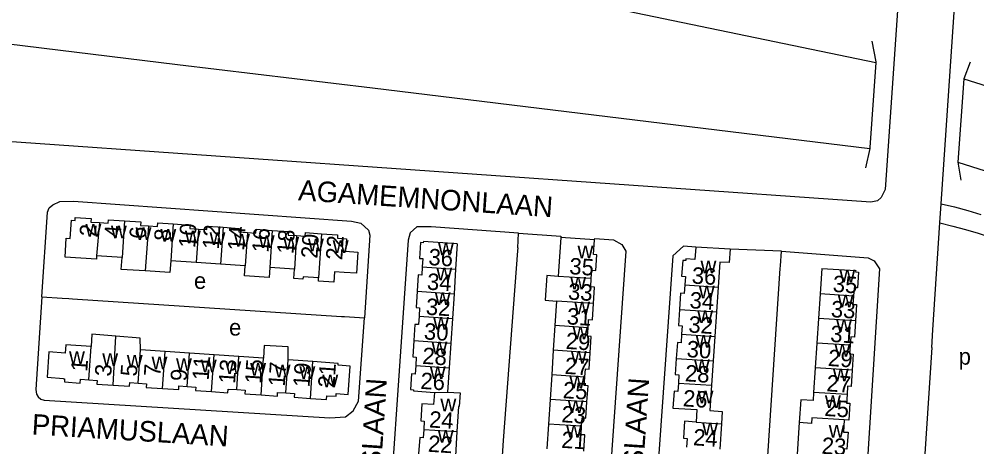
# Model space of a CAD drawing. Extents: x 161773 to 163836, y 384796 to 386521.
# Drawn here: x 162231.1 to 162464.1, y 385536.8 to 385640.8 of the extents above; entities that cross this region are included whole.
import ezdxf

# ---------------------------------------------------------------- set-up
doc = ezdxf.new("R2010")
doc.units = 0
for name, color, linetype in [('BLT_Basislijn', 7, 'Continuous'), ('BLT_Bebouwing', 7, 'Continuous'), ('BLT_Centroide', 7, 'Continuous'), ('BLT_Huisnummer', 7, 'Continuous'), ('BLT_Huisnummer_ tussenligend', 7, 'Continuous'), ('BLT_Onderverdeling_panden', 7, 'Continuous'), ('BLT_Straatnaam', 7, 'Continuous')]:
    doc.layers.add(name, color=color, linetype=linetype)

msp = doc.modelspace()

# ---------------------------------------------------------------- linework, layer by layer
at = {"layer": 'BLT_Basislijn'}
for p, q in [((162317.63, 385655.58), (162439.53, 385630.3)), ((162455.44, 385595.95), (162458.85, 385647.17)), ((162462.45, 385630.37), (162460.94, 385626.3)), ((162460.94, 385626.3), (162459.48, 385606.08)), ((162460.94, 385626.3), (162577.56, 385589.09)), ((162317.05, 385624.1), (162438.01, 385609.35)), ((162438.01, 385609.35), (162436.97, 385604.71)), ((162459.48, 385606.08), (162568.47, 385571.39)), ((162459.48, 385606.08), (162460.19, 385601.65)), ((162455.11, 385591.28), (162455.44, 385595.95)), ((162453.41, 385565.26), (162455.11, 385591.28)), ((162352.37, 385585.22), (162352.6, 385588.82)), ((162416.29, 385580.88), (162416.57, 385584.43)), ((162236.59, 385573.34), (162241.5, 385572.97)), ((162241.5, 385572.97), (162243.11, 385572.86)), ((162453.14, 385560.96), (162453.41, 385565.26)), ((162453.14, 385560.96), (162451.4, 385535.15))]:
    msp.add_line(p, q, dxfattribs=at)
for points in [[(162446.19, 385662.98), (162441.79, 385599.38), (162440.77, 385597.42), (162439.88, 385596.67), (162438.29, 385596.3), (162225.72, 385611.21)], [(162219.86, 385635.91), (162269.55, 385629.78), (162317.05, 385624.1)], [(162438.57, 385635.47), (162439.54, 385630.47), (162439.53, 385630.3)], [(162439.53, 385630.3), (162438.06, 385609.58), (162438.01, 385609.35)], [(162236.59, 385573.34), (162237.99, 385593.89), (162238.38, 385594.97), (162239.27, 385595.66), (162240.95, 385596.48)], [(162240.95, 385596.48), (162244.29, 385596.54), (162311.89, 385591.7), (162314.21, 385591.24), (162316.1, 385589.55), (162316.37, 385588.32), (162315.09, 385568.17)], [(162455.44, 385595.95), (162458.67, 385595.16), (162461.89, 385594.29), (162465.08, 385593.35)], [(162455.11, 385591.28), (162458.23, 385590.52), (162461.34, 385589.68), (162464.43, 385588.76), (162467.5, 385587.77), (162470.53, 385586.7), (162473.55, 385585.56), (162476.53, 385584.34), (162479.48, 385583.05), (162482.4, 385581.68), (162485.28, 385580.25), (162488.12, 385578.74), (162490.93, 385577.16), (162497.53, 385573.15)], [(162352.6, 385588.82), (162331.35, 385590.34), (162327.84, 385590.35), (162326.21, 385588.84), (162325.71, 385587.09), (162319.43, 385496.47), (162318.42, 385473.09), (162319.18, 385471.31), (162321.51, 385470.26), (162326.73, 385469.96)], [(162371.07, 385587.15), (162371.1, 385587.49), (162375.7, 385587.16), (162377.7, 385586.01), (162378.66, 385584.37), (162370.58, 385469.39), (162368.62, 385467.29), (162344.38, 385468.56)], [(162352.6, 385588.82), (162362.88, 385588.08), (162362.85, 385587.71)], [(162352.37, 385585.22), (162352.32, 385584.51), (162348.85, 385538.38), (162344.58, 385473.66)], [(162395.69, 385585.39), (162392.74, 385585.63), (162390.11, 385583.26), (162382.55, 385476.72), (162382.35, 385468.26), (162382.51, 385467.58), (162384.26, 385466.04), (162390.68, 385465.7)], [(162416.57, 385584.43), (162404.05, 385584.87)], [(162416.57, 385584.43), (162437.66, 385582.79), (162439.1, 385582.08), (162440.36, 385580.08), (162432.98, 385462.84)], [(162408.9, 385469.26), (162408.9, 385469.41), (162416.24, 385580.21), (162416.29, 385580.88)], [(162236.59, 385573.34), (162235.09, 385550.76), (162235.26, 385549.65), (162235.7, 385548.98), (162236.36, 385548.44), (162237.13, 385548.2)], [(162243.11, 385572.86), (162244.01, 385572.79), (162309.46, 385568.54)], [(162237.13, 385548.2), (162306.66, 385543.92), (162310.44, 385544.14), (162312.35, 385545.57), (162313.62, 385547.96), (162315.09, 385568.17)], [(162309.46, 385568.54), (162310.19, 385568.49), (162315.09, 385568.17)]]:
    msp.add_lwpolyline(points, dxfattribs=at)
at = {"layer": 'BLT_Bebouwing'}
for p, q in [((162404.05, 385584.87), (162395.69, 385585.39)), ((162256.11, 385582.84), (162249.91, 385583.25)), ((162274.12, 385581.65), (162267.93, 385582.05)), ((162280.08, 385581.25), (162274.12, 385581.65)), ((162286.05, 385580.86), (162280.08, 385581.25)), ((162298.05, 385580.06), (162292.06, 385580.46)), ((162337.26, 385580.05), (162336.87, 385574.07)), ((162401.16, 385575.65), (162400.75, 385569.64)), ((162336.87, 385574.07), (162336.47, 385568.05)), ((162425.93, 385574.03), (162425.54, 385568.05)), ((162361.83, 385572.29), (162361.43, 385566.3)), ((162336.47, 385568.05), (162336.08, 385562.06)), ((162400.75, 385569.64), (162400.35, 385563.64)), ((162425.54, 385568.05), (162425.14, 385562.06)), ((162361.43, 385566.3), (162361.03, 385560.3)), ((162400.35, 385563.64), (162399.95, 385557.71)), ((162248.56, 385561.22), (162242.43, 385561.64)), ((162336.08, 385562.06), (162335.68, 385556.03)), ((162425.14, 385562.06), (162424.75, 385556.05)), ((162266.55, 385560), (162260.56, 385560.4)), ((162272.52, 385559.59), (162266.55, 385560)), ((162278.51, 385559.18), (162272.52, 385559.59)), ((162284.53, 385558.78), (162278.51, 385559.18)), ((162290.54, 385558.37), (162284.53, 385558.78)), ((162361.03, 385560.3), (162360.64, 385554.31)), ((162302.52, 385557.55), (162296.52, 385557.96)), ((162308.71, 385557.13), (162302.52, 385557.55)), ((162399.95, 385557.71), (162399.55, 385551.79)), ((162335.68, 385556.03), (162335.3, 385550.13)), ((162360.64, 385554.31), (162360.24, 385548.35)), ((162424.75, 385556.05), (162424.35, 385550.06)), ((162399.55, 385551.79), (162399.13, 385545.66)), ((162360.24, 385548.35), (162359.84, 385542.37)), ((162399.13, 385545.66), (162402.15, 385545.46)), ((162402.15, 385545.46), (162401.95, 385542.43)), ((162359.84, 385542.37), (162359.44, 385536.34)), ((162401.95, 385542.43), (162401.53, 385536.24)), ((162337.59, 385540.52), (162337.2, 385534.55))]:
    msp.add_line(p, q, dxfattribs=at)
for points in [[(162242.22, 385582.95), (162242.52, 385587.56), (162243.51, 385587.5), (162243.81, 385591.96), (162244.67, 385591.9), (162244.71, 385592.62), (162248.57, 385592.36), (162248.51, 385591.49), (162250.6, 385591.35)], [(162250.6, 385591.35), (162252.7, 385591.21), (162252.76, 385592.06), (162256.7, 385591.8)], [(162256.7, 385591.8), (162260.64, 385591.54), (162260.59, 385590.68), (162262.5, 385590.56)], [(162262.5, 385590.56), (162264.71, 385590.41), (162264.77, 385591.26), (162268.53, 385591.02)], [(162268.53, 385591.02), (162272.65, 385590.74), (162272.6, 385589.93), (162274.66, 385589.79)], [(162274.66, 385589.79), (162276.72, 385589.65), (162276.77, 385590.47), (162280.68, 385590.21)], [(162280.68, 385590.21), (162284.58, 385589.95), (162284.53, 385589.1), (162286.59, 385588.96)], [(162286.59, 385588.96), (162288.66, 385588.82), (162288.72, 385589.72), (162292.65, 385589.46)], [(162292.65, 385589.46), (162296.59, 385589.2), (162296.53, 385588.34), (162298.58, 385588.2)], [(162298.58, 385588.2), (162300.64, 385588.07), (162300.7, 385588.92), (162304.62, 385588.66)], [(162304.62, 385588.66), (162308.56, 385588.4), (162308.5, 385587.56), (162310.7, 385587.41), (162310.5, 385584.37), (162313.5, 385584.17), (162313.16, 385579.07), (162310.16, 385579.26)], [(162337.66, 385586.23), (162329.42, 385586.77), (162329.4, 385586.47), (162328.69, 385586.51), (162328.44, 385582.66), (162329.27, 385582.6), (162329.13, 385580.58)], [(162362.85, 385587.71), (162362.31, 385579.52), (162362.23, 385578.28)], [(162371.07, 385587.15), (162362.85, 385587.71)], [(162370.27, 385577.75), (162370.4, 385579.79), (162371.35, 385579.72), (162371.6, 385583.55), (162370.83, 385583.6), (162371.07, 385587.15)], [(162337.66, 385586.23), (162337.34, 385581.24), (162337.26, 385580.05)], [(162395.69, 385585.39), (162395.5, 385582.4), (162393.28, 385582.54), (162393.27, 385582.13), (162392.52, 385582.18), (162392.26, 385578.32), (162393.17, 385578.26), (162393.03, 385576.2)], [(162404.05, 385584.87), (162403.85, 385581.63), (162401.57, 385581.77), (162401.16, 385575.65)], [(162249.91, 385583.25), (162249.85, 385582.45), (162242.22, 385582.95)], [(162261.73, 385579.61), (162255.89, 385579.96), (162256.11, 385582.84)], [(162267.93, 385582.05), (162267.74, 385579.21), (162261.73, 385579.61)], [(162292.06, 385580.46), (162291.88, 385578.01), (162285.87, 385578.41), (162286.05, 385580.86)], [(162303.92, 385577.92), (162300.13, 385578.18), (162300.1, 385577.62), (162297.87, 385577.77), (162298.05, 385580.06)], [(162329.13, 385580.58), (162329, 385578.57), (162328.15, 385578.62), (162327.89, 385574.65)], [(162426.34, 385580.21), (162426.01, 385575.22), (162425.93, 385574.03)], [(162426.34, 385580.21), (162434.61, 385579.67), (162434.59, 385579.36), (162435.33, 385579.31), (162435.08, 385575.47), (162434.21, 385575.53), (162434.08, 385573.49)], [(162310.16, 385579.26), (162307.83, 385579.42), (162307.66, 385576.89), (162303.87, 385577.14), (162303.92, 385577.92)], [(162362.23, 385578.28), (162359.49, 385578.5), (162359.09, 385572.52), (162361.83, 385572.29)], [(162370.79, 385571.7), (162371.05, 385575.65), (162370.13, 385575.71), (162370.27, 385577.75)], [(162393.03, 385576.2), (162392.89, 385574.15), (162392, 385574.21), (162391.73, 385570.25)], [(162327.89, 385574.65), (162327.63, 385570.68), (162328.49, 385570.63), (162328.36, 385568.58)], [(162434.08, 385573.49), (162433.94, 385571.46), (162434.8, 385571.4), (162434.54, 385567.46)], [(162369.49, 385565.76), (162369.62, 385567.81), (162370.53, 385567.75), (162370.79, 385571.7)], [(162391.73, 385570.25), (162391.46, 385566.3), (162392.39, 385566.23), (162392.25, 385564.19)], [(162328.36, 385568.58), (162328.23, 385566.54), (162327.35, 385566.6), (162327.09, 385562.65)], [(162369.98, 385559.7), (162370.24, 385563.65), (162369.35, 385563.71), (162369.49, 385565.76)], [(162434.54, 385567.46), (162434.28, 385563.52), (162433.41, 385563.58), (162433.28, 385561.52)], [(162254.57, 385563.75), (162248.78, 385564.2), (162248.56, 385561.22)], [(162260.56, 385560.4), (162260.52, 385563.29), (162254.57, 385563.75)], [(162392.25, 385564.19), (162392.12, 385562.15), (162391.22, 385562.21), (162390.96, 385558.32)], [(162242.43, 385561.64), (162242.29, 385559.64), (162238.3, 385559.91), (162237.88, 385553.73), (162241.87, 385553.45), (162241.87, 385553.37), (162242.13, 385553.35), (162242.08, 385552.6), (162245.91, 385552.34), (162245.97, 385553.27), (162248.01, 385553.13)], [(162296.52, 385557.96), (162296.49, 385561.12), (162290.67, 385561.49), (162290.54, 385558.37)], [(162327.09, 385562.65), (162326.83, 385558.71), (162327.69, 385558.65), (162327.55, 385556.57)], [(162433.28, 385561.52), (162433.14, 385559.46), (162434.02, 385559.4), (162433.76, 385555.46)], [(162368.7, 385553.78), (162368.83, 385555.81), (162369.72, 385555.75), (162369.98, 385559.7)], [(162301.92, 385548.62), (162305.88, 385548.36), (162305.94, 385549.27), (162308.17, 385549.11), (162308.21, 385549.77), (162311.13, 385549.57), (162311.59, 385556.45), (162308.68, 385556.65), (162308.71, 385557.13)], [(162327.55, 385556.57), (162327.42, 385554.49), (162326.55, 385554.54), (162326.3, 385550.73), (162327.04, 385550.68), (162327.02, 385550.41), (162332.1, 385550.08)], [(162390.96, 385558.32), (162390.7, 385554.42), (162391.6, 385554.36), (162391.46, 385552.34)], [(162433.76, 385555.46), (162433.5, 385551.51), (162432.64, 385551.56), (162432.51, 385549.52)], [(162248.01, 385553.13), (162250.05, 385552.99), (162249.99, 385552.09), (162253.94, 385551.82)], [(162253.94, 385551.82), (162257.89, 385551.55), (162257.96, 385552.45), (162260.01, 385552.31)], [(162260.01, 385552.31), (162262.06, 385552.17), (162262, 385551.28), (162265.94, 385551.01)], [(162265.94, 385551.01), (162269.88, 385550.74), (162269.94, 385551.65), (162271.97, 385551.51)], [(162369.22, 385547.76), (162369.48, 385551.68), (162368.56, 385551.74), (162368.7, 385553.78)], [(162391.46, 385552.34), (162391.32, 385550.32), (162390.4, 385550.38), (162390.12, 385546.27), (162395.96, 385545.87)], [(162271.97, 385551.51), (162274.01, 385551.37), (162273.95, 385550.52), (162277.9, 385550.25)], [(162277.9, 385550.25), (162281.86, 385549.98), (162281.92, 385550.89), (162283.99, 385550.75)], [(162283.99, 385550.75), (162286.05, 385550.61), (162285.99, 385549.7), (162289.93, 385549.44)], [(162289.93, 385549.44), (162293.88, 385549.17), (162293.94, 385550.06), (162295.98, 385549.92)], [(162295.98, 385549.92), (162298.02, 385549.78), (162297.96, 385548.89), (162301.92, 385548.62)], [(162332.1, 385550.08), (162331.9, 385547.09), (162329.04, 385547.27), (162328.77, 385543.13), (162329.62, 385543.07), (162329.49, 385541.06)], [(162335.3, 385550.13), (162338.36, 385549.93), (162338.14, 385546.6), (162337.99, 385546.61), (162337.59, 385540.52)], [(162424.35, 385550.06), (162424.22, 385548.07), (162421.23, 385548.27), (162420.86, 385542.71)], [(162432.51, 385549.52), (162432.37, 385547.48), (162433.22, 385547.42), (162432.95, 385543.33), (162431.81, 385543.4)], [(162367.91, 385541.84), (162368.04, 385543.89), (162368.96, 385543.83), (162369.22, 385547.76)], [(162395.96, 385545.87), (162395.76, 385542.86)], [(162395.76, 385542.86), (162392.96, 385543.05), (162392.68, 385538.92), (162393.58, 385538.86), (162393.43, 385536.78)], [(162420.86, 385542.71), (162420.36, 385535.05), (162423.32, 385534.84)], [(162431.81, 385543.4), (162431.62, 385540.43), (162432.76, 385540.36), (162432.49, 385536.28), (162431.62, 385536.33), (162431.48, 385534.28)], [(162329.49, 385541.06), (162329.36, 385539.04), (162328.52, 385539.1), (162328.26, 385535.14)], [(162368.43, 385535.74), (162368.7, 385539.72), (162367.77, 385539.78), (162367.91, 385541.84)]]:
    msp.add_lwpolyline(points, dxfattribs=at)
at = {"layer": 'BLT_Onderverdeling_panden'}
for p, q in [((162250.6, 385591.35), (162249.91, 385583.25)), ((162256.7, 385591.8), (162256.11, 385582.84)), ((162262.5, 385590.56), (162261.73, 385579.61)), ((162268.53, 385591.02), (162267.93, 385582.05)), ((162274.66, 385589.79), (162274.12, 385581.65)), ((162280.68, 385590.21), (162280.08, 385581.25)), ((162286.59, 385588.96), (162286.05, 385580.86)), ((162292.65, 385589.46), (162292.06, 385580.46)), ((162298.58, 385588.2), (162298.05, 385580.06)), ((162304.62, 385588.66), (162303.92, 385577.92)), ((162329.13, 385580.58), (162337.26, 385580.05)), ((162370.27, 385577.75), (162362.23, 385578.28)), ((162393.03, 385576.2), (162401.16, 385575.65)), ((162327.89, 385574.65), (162336.87, 385574.07)), ((162434.08, 385573.49), (162425.93, 385574.03)), ((162370.79, 385571.7), (162361.83, 385572.29)), ((162391.73, 385570.25), (162400.75, 385569.64)), ((162328.36, 385568.58), (162336.47, 385568.05)), ((162434.54, 385567.46), (162425.54, 385568.05)), ((162369.49, 385565.76), (162361.43, 385566.3)), ((162253.94, 385551.82), (162254.57, 385563.75)), ((162392.25, 385564.19), (162400.35, 385563.64)), ((162248.01, 385553.13), (162248.56, 385561.22)), ((162327.09, 385562.65), (162336.08, 385562.06)), ((162433.28, 385561.52), (162425.14, 385562.06)), ((162260.01, 385552.31), (162260.56, 385560.4)), ((162265.94, 385551.01), (162266.55, 385560)), ((162271.97, 385551.51), (162272.52, 385559.59)), ((162277.9, 385550.25), (162278.51, 385559.18)), ((162283.99, 385550.75), (162284.53, 385558.78)), ((162369.98, 385559.7), (162361.03, 385560.3)), ((162289.93, 385549.44), (162290.54, 385558.37)), ((162295.98, 385549.92), (162296.52, 385557.96)), ((162301.92, 385548.62), (162302.52, 385557.55)), ((162327.55, 385556.57), (162335.68, 385556.03)), ((162390.96, 385558.32), (162399.95, 385557.71)), ((162368.7, 385553.78), (162360.64, 385554.31)), ((162433.76, 385555.46), (162424.75, 385556.05)), ((162391.46, 385552.34), (162399.55, 385551.79)), ((162332.1, 385550.08), (162335.3, 385550.13)), ((162432.51, 385549.52), (162424.35, 385550.06)), ((162369.22, 385547.76), (162360.24, 385548.35)), ((162367.91, 385541.84), (162359.84, 385542.37)), ((162395.76, 385542.86), (162401.95, 385542.43)), ((162329.49, 385541.06), (162337.59, 385540.52))]:
    msp.add_line(p, q, dxfattribs=at)
msp.add_lwpolyline([(162431.81, 385543.4), (162423.92, 385543.92), (162423.83, 385542.52), (162420.86, 385542.71)], dxfattribs=at)

# ---------------------------------------------------------------- texts
at = {"layer": 'BLT_Centroide'}
for s, p in [('w', (162247.19, 385587.95)), ('w', (162253.39, 385587.53)), ('w', (162259.38, 385587.12)), ('w', (162265.41, 385586.72)), ('w', (162271.39, 385586.31)), ('w', (162277.39, 385585.94)), ('w', (162283.34, 385585.53)), ('w', (162289.36, 385585.16)), ('w', (162295.31, 385584.77)), ('w', (162301.33, 385584.36)), ('w', (162307.36, 385583.95)), ('w', (162332.98, 385583.41)), ('w', (162366.92, 385582.7)), ('w', (162396.85, 385579.03)), ('w', (162332.57, 385577.31)), ('w', (162430.64, 385576.84)), ('e', (162273.6, 385575.23)), ('w', (162365.14, 385575.09)), ('w', (162396.44, 385572.91)), ('w', (162332.18, 385571.34)), ('w', (162430.23, 385570.75)), ('w', (162366.11, 385569.03)), ('w', (162331.78, 385565.31)), ('w', (162396.04, 385566.94)), ('e', (162282.14, 385563.88)), ('w', (162365.71, 385563)), ('w', (162429.84, 385564.78)), ('w', (162395.66, 385560.94)), ('w', (162331.39, 385559.34)), ('w', (162429.45, 385558.75)), ('w', (162243.19, 385557)), ('w', (162251.28, 385556.52)), ('w', (162257.25, 385556.11)), ('w', (162263.28, 385555.7)), ('w', (162365.3, 385557.03)), ('p', (162459.67, 385556.81)), ('w', (162269.23, 385555.3)), ('w', (162275.25, 385554.92)), ('w', (162281.22, 385554.52)), ('w', (162287.27, 385554.11)), ('w', (162293.22, 385553.7)), ('w', (162299.25, 385553.3)), ('w', (162330.98, 385553.31)), ('w', (162395.25, 385555.06)), ('w', (162304.83, 385551.32)), ('w', (162364.93, 385551.03)), ('w', (162429.05, 385552.78)), ('w', (162396.14, 385547.44)), ('w', (162427.12, 385546.25)), ('w', (162333.56, 385545.44)), ('w', (162364.54, 385545.09)), ('w', (162397.25, 385539.66)), ('w', (162332.92, 385537.81)), ('w', (162364.14, 385539.06)), ('w', (162428.05, 385539.08))]:
    msp.add_text(s, height=4, dxfattribs=at).set_placement(p)
at = {"layer": 'BLT_Huisnummer'}
for s, rotation, p in [('2', 86.2144, (162249.73, 385587.87)), ('6', 86.2135, (162261.84, 385587.28)), ('10', 86.2174, (162273.86, 385585.12)), ('14', 86.2186, (162285.77, 385584.42)), ('18', 86.2189, (162297.78, 385583.62)), ('22', 86.2163, (162309.66, 385582.16)), ('36', 356.2468, (162330.56, 385581.05)), ('35', 356.1996, (162364.84, 385578.83)), ('36', 356.1298, (162394.63, 385576.57)), ('35', 356.2284, (162428.95, 385574.52)), ('30', 356.2548, (162329.47, 385562.97)), ('29', 356.194, (162363.97, 385560.67)), ('30', 356.1263, (162393.4, 385558.67)), ('29', 356.2224, (162427.78, 385556.51)), ('1', 86.0947, (162247.62, 385555)), ('5', 86.1115, (162259.69, 385553.86)), ('13', 86.1216, (162283.58, 385552.08)), ('17', 86.1165, (162295.67, 385551.41)), ('21', 86.111, (162307.75, 385551.09)), ('9', 86.1144, (162271.84, 385552.69)), ('26', 356.2488, (162328.61, 385550.94)), ('25', 356.1972, (162363.26, 385548.69)), ('26', 356.1254, (162392.48, 385546.7)), ('25', 356.2312, (162426.91, 385544.36)), ('21', 356.1954, (162362.9, 385536.61)), ('22', 356.2491, (162330.46, 385535.65))]:
    msp.add_text(s, height=4, rotation=rotation, dxfattribs=at).set_placement(p)
at = {"layer": 'BLT_Huisnummer_ tussenligend'}
for s, rotation, p in [('4', 86.2144, (162255.76, 385587.6)), ('8', 86.2135, (162267.87, 385586.77)), ('12', 86.2174, (162279.64, 385584.79)), ('16', 86.2186, (162291.72, 385583.99)), ('20', 86.2189, (162303.62, 385582.55)), ('34', 356.2548, (162330.21, 385575.06)), ('33', 356.194, (162364.53, 385572.67)), ('32', 356.2548, (162329.95, 385568.97)), ('34', 356.1263, (162394.11, 385570.55)), ('31', 356.194, (162364.23, 385566.64)), ('33', 356.2224, (162428.5, 385568.39)), ('32', 356.1263, (162393.82, 385564.66)), ('31', 356.2224, (162428.34, 385562.37)), ('28', 356.2488, (162329.08, 385557.03)), ('11', 86.1144, (162277.17, 385552.91)), ('3', 86.0947, (162253.45, 385553.86)), ('7', 86.1115, (162265.38, 385553.85)), ('15', 86.1216, (162289.96, 385552.08)), ('19', 86.1165, (162301.7, 385551.24)), ('27', 356.1972, (162363.72, 385554.6)), ('28', 356.1254, (162392.99, 385552.79)), ('27', 356.2312, (162427.41, 385550.35)), ('24', 356.2491, (162330.72, 385541.56)), ('23', 356.1954, (162362.92, 385542.83)), ('24', 356.1888, (162394.96, 385537.22)), ('23', 356.2308, (162426.23, 385535.17))]:
    msp.add_text(s, height=4, rotation=rotation, dxfattribs=at).set_placement(p)
at = {"layer": 'BLT_Straatnaam'}
for s, height, rotation, p in [('AGAMEMNONLAAN', 4.9999, 356.1621, (162298.87, 385596.8)), ('CALCHASLAAN', 4.9999, 86.2242, (162317.32, 385504.38)), ('ADMETUSLAAN', 5, 86.1839, (162381.03, 385503.41)), ('PRIAMUSLAAN', 5, 356.4846, (162234.03, 385539.84))]:
    msp.add_text(s, height=height, rotation=rotation, dxfattribs=at).set_placement(p)

doc.saveas('drawing.dxf')
